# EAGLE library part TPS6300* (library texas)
HIGH EFFICIENT SINGLE INDUCTOR BUCK-BOOST CONVERTER WITH 1.8-A SWITCHES Source: http://focus.ti.com/lit/ds/symlink/tps63001.pdf
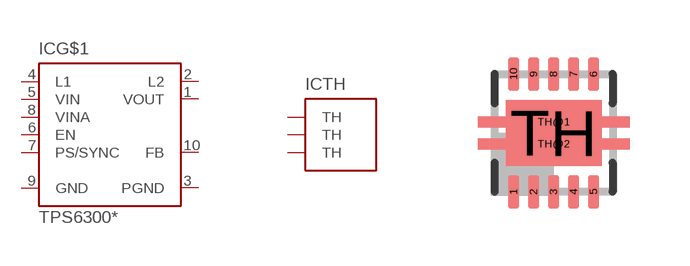
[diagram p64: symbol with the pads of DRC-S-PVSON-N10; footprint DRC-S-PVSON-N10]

Designator prefix IC; gates G$1=TPS6300X TH=THERMAL3

## TPS6300 (MPN: TPS63000DRCTG4; OC_FARNELL: 1511852; OC_NEWARK: 59M7217)  [DRC-S-PVSON-N10]
1  G$1:VOUT  out
2  G$1:L2  pas
3  G$1:PGND  pwr
4  G$1:L1  pas
5  G$1:VIN  in
6  G$1:EN  in
7  G$1:PS/SYNC  in
8  G$1:VINA  in
9  G$1:GND  pwr
10  G$1:FB  in
TH  TH:TH  pas
TH@1  TH:TH  pas
TH@2  TH:TH  pas

## Footprint DRC-S-PVSON-N10 (pad centres in mm)
DRC (S-PVSON-N10) Source: http://focus.ti.com/lit/ds/symlink/tps63001.pdf
smd 0.28 x 0.85: 1 -1,-1.475; 2 -0.5,-1.475; 3 0,-1.475; 4 0.5,-1.475; 5 1,-1.475; 6 1,1.475; 7 0.5,1.475; 8 0,1.475; 9 -0.5,1.475; 10 -1,1.475
smd 2.4 x 1.65: TH 0,0
smd 3.8 x 0.28: TH@1 0,0.275; TH@2 0,-0.275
